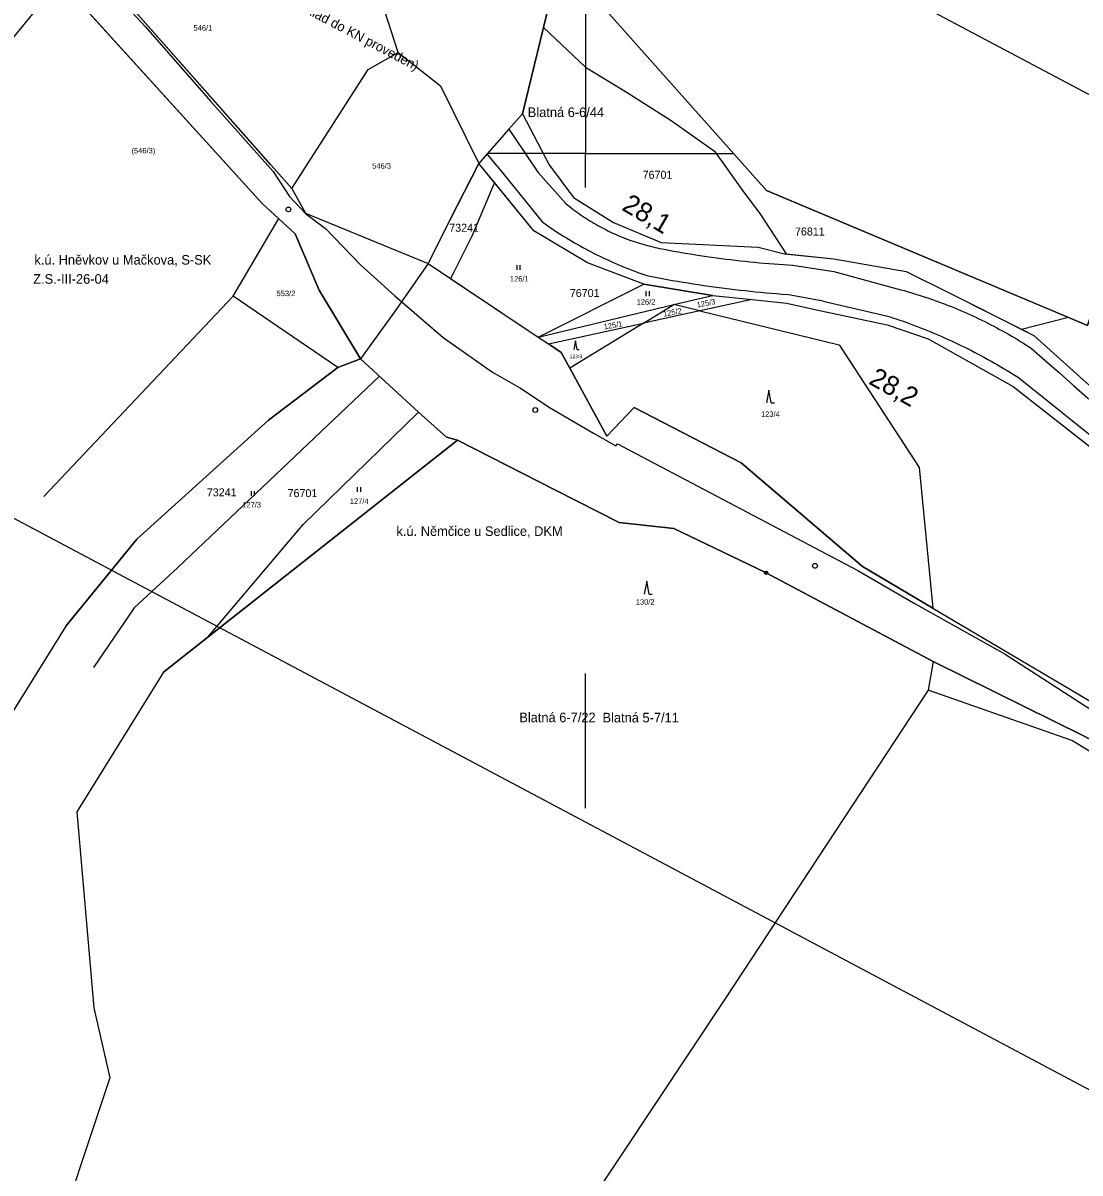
# Model space of a CAD drawing. Extents: x -794765 to -785424, y -1118958 to -1108731.
# Drawn here: x -790175.8 to -789845.5, y -1114318.6 to -1113959.3 of the extents above; entities that cross this region are included whole.
import ezdxf

# ---------------------------------------------------------------- set-up
doc = ezdxf.new("R2010")
doc.units = 0
for name, color, linetype in [('Level 66', 7, 'Continuous'), ('Level 71', 7, 'Continuous'), ('Level 73', 7, 'Continuous'), ('Level 75', 7, 'Continuous'), ('Level 76', 7, 'Continuous'), ('Level 77', 7, 'Continuous'), ('Level 78', 7, 'Continuous'), ('Level 81', 7, 'Continuous'), ('Vrstva 1', 7, 'Continuous'), ('Vrstva 53', 7, 'Continuous')]:
    doc.layers.add(name, color=color, linetype=linetype)

msp = doc.modelspace()

# ---------------------------------------------------------------- linework, layer by layer
at = {"layer": 'Level 66'}
for p, q in [((-790021.43, -1114036.41), (-790021.43, -1114034.91)), ((-790020.43, -1114036.41), (-790020.43, -1114034.91)), ((-789981.08, -1114044.59), (-789981.08, -1114043.09)), ((-789980.08, -1114044.59), (-789980.08, -1114043.09)), ((-790003.17, -1114058.6), (-790003.67, -1114061.28)), ((-790002.67, -1114061.28), (-790003.17, -1114058.6)), ((-790002.67, -1114061.28), (-790002, -1114061.28)), ((-789942.76, -1114073.96), (-789943.51, -1114077.96)), ((-789942.01, -1114077.96), (-789942.76, -1114073.96)), ((-789942.01, -1114077.96), (-789941.01, -1114077.96)), ((-790071.27, -1114105.77), (-790071.27, -1114104.27)), ((-790070.27, -1114105.77), (-790070.27, -1114104.27)), ((-790104.44, -1114107.04), (-790104.44, -1114105.54)), ((-790103.44, -1114107.04), (-790103.44, -1114105.54)), ((-789980.9, -1114133.71), (-789981.65, -1114137.71)), ((-789980.15, -1114137.71), (-789980.9, -1114133.71)), ((-789980.15, -1114137.71), (-789979.16, -1114137.71))]:
    msp.add_line(p, q, dxfattribs=at)
at = {"layer": 'Level 71'}
msp.add_line((-789259.98, -1114291.21), (-790231.6, -1113775.02), dxfattribs=at)
msp.add_lwpolyline([(-790360.41, -1114017.5), (-789388.79, -1114533.68), (-789259.98, -1114291.21)], dxfattribs=at)
at = {"layer": 'Level 75'}
for p, q in [((-790098.6, -1114003.51), (-790153.82, -1113940.85)), ((-790153.82, -1113940.85), (-790091.86, -1114010.99)), ((-790164.37, -1113945.95), (-790182.14, -1113967.7)), ((-790164.37, -1113945.95), (-790101.08, -1114015.62)), ((-790058.56, -1113968.52), (-790063.8, -1113952.28)), ((-790067.98, -1113973.75), (-790058.56, -1113968.52)), ((-790058.56, -1113968.52), (-790045.36, -1113978.94)), ((-790091.86, -1114010.99), (-790067.98, -1113973.75)), ((-790045.36, -1113978.94), (-790033.4, -1114003.11)), ((-790091.86, -1114010.99), (-790087.54, -1114018.7)), ((-790101.08, -1114015.62), (-790090.8, -1114025.12)), ((-790087.54, -1114018.7), (-790049.23, -1114034.44)), ((-790110.17, -1114044.62), (-790095.88, -1114020.36)), ((-790090.8, -1114025.12), (-790083.26, -1114042.7)), ((-790049.23, -1114034.44), (-790014.82, -1114057.41)), ((-790083.26, -1114042.7), (-790070.36, -1114064.18)), ((-790014.82, -1114057.41), (-789981.78, -1114040.88)), ((-789981.78, -1114040.88), (-789960.34, -1114044.38)), ((-790110.17, -1114044.62), (-790169.33, -1114107.22)), ((-790077.41, -1114066.92), (-790110.17, -1114044.62)), ((-790014.82, -1114057.41), (-789972.39, -1114047.26)), ((-789981.86, -1114053.04), (-789972.39, -1114047.26)), ((-789972.39, -1114047.26), (-789960.34, -1114044.38)), ((-789964.33, -1114049.22), (-789972.39, -1114047.26)), ((-789947.95, -1114045.65), (-789964.33, -1114049.22)), ((-789960.34, -1114044.38), (-789947.95, -1114045.65)), ((-789964.33, -1114049.22), (-789981.86, -1114053.04)), ((-790011.64, -1114059.53), (-789981.86, -1114053.04)), ((-789981.86, -1114053.04), (-790004.95, -1114067.14)), ((-790014.82, -1114057.41), (-790011.64, -1114059.53)), ((-790070.36, -1114064.18), (-790052.2, -1114080.82)), ((-790039.99, -1114089.61), (-790118.12, -1114151.21)), ((-789891.39, -1114158.73), (-789892.98, -1114167.7))]:
    msp.add_line(p, q, dxfattribs=at)
for points in [[(-790019.69, -1113987.62), (-790011.36, -1114003.57), (-790003.8, -1114013.73), (-789991.32, -1114021.6), (-789976.43, -1114027.83), (-789946.04, -1114029.33), (-789937.84, -1114031.36), (-789922.4, -1114032.99), (-789899.76, -1114036.89), (-789886.4, -1114043.52), (-789859.91, -1114056.9), (-789828.1, -1114085.48), (-789766.83, -1114142.08), (-789706.12, -1114193.77), (-789699.87, -1114199.39)], [(-789981.78, -1114040.88), (-789999.38, -1114034.22), (-790016.19, -1114024.23), (-790033.4, -1114003.11)], [(-789947.95, -1114045.65), (-789937.19, -1114046.76), (-789926.39, -1114049.19), (-789905.79, -1114053.58), (-789892.95, -1114057.97), (-789866.38, -1114072.87), (-789837.53, -1114095.45), (-789775.3, -1114149.42), (-789717.99, -1114202.34), (-789674.05, -1114243.92)], [(-789964.33, -1114049.22), (-789920.8, -1114059.79), (-789895.78, -1114098.15), (-789891.43, -1114142.08)], [(-790004.95, -1114067.14), (-790007.66, -1114062.18), (-790011.64, -1114059.53)], [(-789891.43, -1114142.08), (-789913.42, -1114129.06), (-789951.34, -1114096.74), (-789984.83, -1114079.42), (-789993.35, -1114088.34), (-790004.95, -1114067.14)], [(-790118.12, -1114151.21), (-790088.3, -1114115.91), (-790052.2, -1114080.82)], [(-790052.2, -1114080.82), (-790043.48, -1114088.64), (-790039.99, -1114089.61)], [(-790039.99, -1114089.61), (-790009.42, -1114105.25), (-789989.47, -1114115.38), (-789972.38, -1114117.19), (-789943.99, -1114130.82), (-789891.39, -1114158.73)], [(-789891.43, -1114142.08), (-789830.15, -1114178.38), (-789746.5, -1114225.43), (-789721.98, -1114237.82)], [(-790118.12, -1114151.21), (-790131.9, -1114162.08), (-790158.98, -1114205.72), (-790153.67, -1114267.03), (-790148.66, -1114288.87), (-790168.4, -1114348.05)], [(-789891.39, -1114158.73), (-789844.34, -1114181.96), (-789790.24, -1114210.69), (-789730.23, -1114243.59)], [(-789892.98, -1114167.7), (-789956.24, -1114263.94), (-790065.9, -1114428.82), (-790175.53, -1114594.15)], [(-789832.77, -1114192.7), (-789848.03, -1114183.45), (-789892.98, -1114167.7)]]:
    msp.add_lwpolyline(points, dxfattribs=at)
at = {"layer": 'Level 77'}
for p, q in [((-790023.95, -1113992.43), (-790022.21, -1113995.02)), ((-790022.21, -1113995.02), (-790014.92, -1114005.9)), ((-790027.64, -1114003.95), (-790030.75, -1114000.11)), ((-790027.64, -1114003.95), (-790013.47, -1114021.46)), ((-790014.92, -1114005.9), (-790006.2, -1114015.61)), ((-789935.2, -1114034.92), (-789922.4, -1114036.87)), ((-789922.4, -1114036.87), (-789901.48, -1114042.61)), ((-789925.75, -1114046.15), (-789937.07, -1114044.08)), ((-789925.75, -1114046.15), (-789905.15, -1114050.98)), ((-789835.77, -1114093.33), (-789865.26, -1114069.71))]:
    msp.add_line(p, q, dxfattribs=at)
for points in [[(-790006.2, -1114015.61), (-790005.65, -1114016.06), (-790005.09, -1114016.51), (-790004.54, -1114016.96), (-790003.97, -1114017.39), (-790003.4, -1114017.82), (-790002.83, -1114018.25), (-790002.25, -1114018.66), (-790001.67, -1114019.08), (-790001.08, -1114019.48), (-790000.49, -1114019.88), (-789999.89, -1114020.27), (-789999.29, -1114020.66), (-789998.69, -1114021.04), (-789998.08, -1114021.41), (-789997.47, -1114021.78), (-789996.85, -1114022.14), (-789996.23, -1114022.49), (-789995.6, -1114022.84), (-789994.98, -1114023.18), (-789994.35, -1114023.51), (-789993.71, -1114023.83), (-789993.07, -1114024.16), (-789992.43, -1114024.47), (-789991.79, -1114024.77), (-789991.14, -1114025.07), (-789990.49, -1114025.36), (-789989.83, -1114025.65), (-789989.18, -1114025.92), (-789988.52, -1114026.19), (-789987.85, -1114026.46), (-789987.19, -1114026.71), (-789986.52, -1114026.96), (-789985.84, -1114027.2), (-789985.17, -1114027.44), (-789984.49, -1114027.66), (-789983.82, -1114027.88), (-789983.13, -1114028.09), (-789982.45, -1114028.3), (-789981.76, -1114028.5), (-789981.08, -1114028.69), (-789980.39, -1114028.87), (-789979.7, -1114029.04), (-789979, -1114029.21), (-789978.31, -1114029.37), (-789977.61, -1114029.52), (-789976.91, -1114029.67)], [(-790013.47, -1114021.46), (-790012.66, -1114022.03), (-790011.85, -1114022.6), (-790011.03, -1114023.16), (-790010.2, -1114023.72), (-790009.38, -1114024.27), (-790008.54, -1114024.81), (-790007.71, -1114025.34), (-790006.87, -1114025.87), (-790006.02, -1114026.39), (-790005.17, -1114026.91), (-790004.32, -1114027.42), (-790003.46, -1114027.92), (-790002.6, -1114028.41), (-790001.74, -1114028.9), (-790000.87, -1114029.38), (-790000, -1114029.85), (-789999.12, -1114030.32), (-789998.24, -1114030.78), (-789997.36, -1114031.23), (-789996.47, -1114031.68), (-789995.58, -1114032.12), (-789994.69, -1114032.55), (-789993.79, -1114032.98), (-789992.89, -1114033.39), (-789991.98, -1114033.8), (-789991.08, -1114034.21), (-789990.17, -1114034.6), (-789989.25, -1114034.99), (-789988.34, -1114035.37), (-789987.42, -1114035.75), (-789986.49, -1114036.11), (-789985.57, -1114036.47), (-789984.64, -1114036.82), (-789983.71, -1114037.17), (-789982.78, -1114037.51), (-789981.84, -1114037.84), (-789980.9, -1114038.16)], [(-789976.91, -1114029.67), (-789975.44, -1114029.96), (-789973.96, -1114030.24), (-789972.48, -1114030.51), (-789971, -1114030.77), (-789969.52, -1114031.03), (-789968.04, -1114031.28), (-789966.56, -1114031.52), (-789965.07, -1114031.76), (-789963.59, -1114031.99), (-789962.1, -1114032.21), (-789960.61, -1114032.42), (-789959.13, -1114032.63), (-789957.64, -1114032.83), (-789956.15, -1114033.02), (-789954.66, -1114033.2), (-789953.16, -1114033.38), (-789951.67, -1114033.55), (-789950.18, -1114033.71), (-789948.68, -1114033.86), (-789947.19, -1114034.01), (-789945.69, -1114034.15), (-789944.19, -1114034.28), (-789942.7, -1114034.41), (-789941.2, -1114034.52), (-789939.7, -1114034.64), (-789938.2, -1114034.74), (-789936.7, -1114034.83), (-789935.2, -1114034.92)], [(-789980.9, -1114038.16), (-789979.29, -1114038.48), (-789977.68, -1114038.78), (-789976.07, -1114039.09), (-789974.46, -1114039.38), (-789972.84, -1114039.67), (-789971.23, -1114039.95), (-789969.61, -1114040.22), (-789967.99, -1114040.48), (-789966.38, -1114040.74), (-789964.76, -1114040.99), (-789963.14, -1114041.23), (-789961.51, -1114041.46), (-789959.89, -1114041.69), (-789958.27, -1114041.91), (-789956.64, -1114042.12), (-789955.01, -1114042.33), (-789953.39, -1114042.52), (-789951.76, -1114042.71), (-789950.13, -1114042.89), (-789948.5, -1114043.07), (-789946.87, -1114043.24), (-789945.24, -1114043.4), (-789943.6, -1114043.55), (-789941.97, -1114043.69), (-789940.34, -1114043.83), (-789938.71, -1114043.96), (-789937.07, -1114044.08)], [(-789901.48, -1114042.61), (-789900.47, -1114042.89), (-789899.47, -1114043.17), (-789898.47, -1114043.46), (-789897.47, -1114043.76), (-789896.47, -1114044.06), (-789895.48, -1114044.37), (-789894.49, -1114044.69), (-789893.5, -1114045.02), (-789892.51, -1114045.35), (-789891.53, -1114045.69), (-789890.54, -1114046.04), (-789889.56, -1114046.4), (-789888.59, -1114046.76), (-789887.61, -1114047.13), (-789886.64, -1114047.5), (-789885.67, -1114047.89), (-789884.71, -1114048.28), (-789883.74, -1114048.68), (-789882.78, -1114049.08), (-789881.82, -1114049.5), (-789880.87, -1114049.91), (-789879.92, -1114050.34), (-789878.97, -1114050.77), (-789878.03, -1114051.21), (-789877.08, -1114051.66), (-789876.15, -1114052.11), (-789875.21, -1114052.57), (-789874.28, -1114053.04), (-789873.35, -1114053.52), (-789872.43, -1114054), (-789871.51, -1114054.49), (-789870.59, -1114054.98), (-789869.68, -1114055.48), (-789868.77, -1114055.99), (-789867.86, -1114056.51), (-789866.96, -1114057.03), (-789866.06, -1114057.55), (-789865.16, -1114058.09), (-789864.27, -1114058.63), (-789863.39, -1114059.18), (-789862.5, -1114059.73), (-789861.62, -1114060.29), (-789860.75, -1114060.86)], [(-789905.15, -1114050.98), (-789904.05, -1114051.34), (-789902.94, -1114051.71), (-789901.84, -1114052.09), (-789900.74, -1114052.47), (-789899.65, -1114052.86), (-789898.56, -1114053.26), (-789897.47, -1114053.66), (-789896.38, -1114054.07), (-789895.29, -1114054.49), (-789894.21, -1114054.92), (-789893.13, -1114055.35), (-789892.06, -1114055.8), (-789890.98, -1114056.24), (-789889.92, -1114056.7), (-789888.85, -1114057.16), (-789887.78, -1114057.63), (-789886.72, -1114058.11), (-789885.67, -1114058.59), (-789884.61, -1114059.08), (-789883.56, -1114059.58), (-789882.51, -1114060.08), (-789881.47, -1114060.6), (-789880.43, -1114061.11), (-789879.39, -1114061.64), (-789878.36, -1114062.17), (-789877.33, -1114062.71), (-789876.3, -1114063.26), (-789875.28, -1114063.81), (-789874.26, -1114064.37), (-789873.24, -1114064.94), (-789872.23, -1114065.51), (-789871.22, -1114066.09), (-789870.22, -1114066.68), (-789869.22, -1114067.27), (-789868.22, -1114067.87), (-789867.23, -1114068.48), (-789866.24, -1114069.09), (-789865.26, -1114069.71)], [(-789860.75, -1114060.86), (-789856.33, -1114064.74), (-789851.91, -1114068.61), (-789847.5, -1114072.5), (-789843.09, -1114076.39), (-789838.69, -1114080.29), (-789834.29, -1114084.19), (-789829.9, -1114088.1), (-789825.52, -1114092.02), (-789821.13, -1114095.94), (-789816.76, -1114099.86), (-789812.39, -1114103.79), (-789808.02, -1114107.73), (-789803.66, -1114111.67), (-789799.3, -1114115.62), (-789794.95, -1114119.57), (-789790.6, -1114123.53), (-789786.26, -1114127.5), (-789781.93, -1114131.47), (-789777.6, -1114135.44), (-789773.27, -1114139.42), (-789768.95, -1114143.41)]]:
    msp.add_lwpolyline(points, dxfattribs=at)
at = {"layer": 'Level 78'}
for p, q in [((-790033.4, -1114003.11), (-790042.39, -1114020.89)), ((-790042.39, -1114020.89), (-790049.23, -1114034.44)), ((-790049.23, -1114034.44), (-790059.73, -1114049.47)), ((-790059.73, -1114049.47), (-790070.36, -1114064.18))]:
    msp.add_line(p, q, dxfattribs=at)
for points in [[(-789943.45, -1114011.64), (-790007.99, -1113939.1), (-790019.69, -1113987.62)], [(-790019.69, -1113987.62), (-790023.95, -1113992.43), (-790030.75, -1114000.11), (-790033.4, -1114003.11)], [(-789834.61, -1114027.84), (-789843.16, -1114053.8), (-789943.45, -1114011.64)], [(-790070.36, -1114064.18), (-790077.41, -1114066.92), (-790099.13, -1114083.32), (-790140.29, -1114120.5), (-790162.46, -1114147.73), (-790179, -1114174.35), (-790192.46, -1114201.21), (-790195.44, -1114214.86), (-790192.12, -1114271.28), (-790194.98, -1114295.25), (-790216.55, -1114326.64), (-790237.66, -1114340.78), (-790265.88, -1114352.25), (-790307.31, -1114357.21), (-790358.52, -1114379.07), (-790378.06, -1114396.2)]]:
    msp.add_lwpolyline(points, dxfattribs=at)
at = {"layer": 'Level 81'}
for p, q in [((-790019.69, -1113987.62), (-790013.2, -1113960.7)), ((-790028.5, -1114009.12), (-790033.4, -1114003.11)), ((-789945.59, -1114018.79), (-789937.34, -1114031.41)), ((-790049.23, -1114034.44), (-790042.18, -1114039.14)), ((-790041.35, -1114037.5), (-790042.18, -1114039.14)), ((-789863.72, -1114054.97), (-789849.48, -1114051.25)), ((-789849.48, -1114051.25), (-789849.33, -1114051.2))]:
    msp.add_line(p, q, dxfattribs=at)
for points in [[(-790013.2, -1113960.7), (-790007.99, -1113939.1), (-789943.45, -1114011.64), (-789849.33, -1114051.2)], [(-790013.2, -1113960.7), (-790000.03, -1113973.03), (-790000, -1113973.05), (-789987.02, -1113981.02), (-789973.21, -1113989.77), (-789959.71, -1113999.32), (-789959.23, -1114000), (-789950.67, -1114012), (-789945.59, -1114018.79)], [(-790019.69, -1113987.62), (-790011.36, -1114003.57), (-790003.8, -1114013.73), (-789991.32, -1114021.6), (-789976.43, -1114027.83), (-789946.04, -1114029.33), (-789937.84, -1114031.36), (-789937.34, -1114031.41)], [(-790049.23, -1114034.44), (-790042.39, -1114020.89), (-790033.4, -1114003.11)], [(-790028.5, -1114009.12), (-790035.41, -1114025.68), (-790041.35, -1114037.5)], [(-789972.39, -1114047.26), (-789960.34, -1114044.38), (-789981.78, -1114040.88), (-789999.38, -1114034.22), (-790016.19, -1114024.23), (-790028.5, -1114009.12)], [(-789937.34, -1114031.41), (-789922.4, -1114032.99), (-789899.76, -1114036.89), (-789886.4, -1114043.52), (-789863.72, -1114054.97)], [(-790042.18, -1114039.14), (-790014.82, -1114057.41), (-789972.39, -1114047.26)], [(-789849.33, -1114051.2), (-789843.16, -1114053.8), (-789841.6, -1114049.06)], [(-789863.72, -1114054.97), (-789859.91, -1114056.9), (-789828.1, -1114085.48), (-789766.83, -1114142.08), (-789706.12, -1114193.77), (-789699.87, -1114199.39), (-789653.29, -1114241.26), (-789626.24, -1114265.44), (-789585.72, -1114278.05), (-789547.28, -1114285.86), (-789509.8, -1114297.51), (-789475.21, -1114308.57), (-789456.17, -1114314.65), (-789451.67, -1114316.09), (-789445.82, -1114299.21), (-789436.06, -1114282.16), (-789435.21, -1114282.44), (-789432.19, -1114273.58), (-789444.18, -1114268.92), (-789455.16, -1114266.24)], [(-790162.46, -1114147.73), (-790140.29, -1114120.5), (-790099.13, -1114083.32), (-790077.41, -1114066.92), (-790070.36, -1114064.18)], [(-790131.9, -1114162.08), (-790118.12, -1114151.21), (-790039.99, -1114089.61), (-790043.48, -1114088.64), (-790052.2, -1114080.82), (-790070.36, -1114064.18)], [(-790064.44, -1114069.6), (-790127.48, -1114129.4), (-790141.06, -1114142.04), (-790153.79, -1114160.6)]]:
    msp.add_lwpolyline(points, dxfattribs=at)
at = {"layer": 'Vrstva 1'}
for p, q in [((-790154.38, -1113942.38), (-790137.55, -1113960.43)), ((-790000, -1113948.08), (-790000, -1114000)), ((-790137.55, -1113960.43), (-790117.25, -1113983.63)), ((-790000, -1114000), (-790030.65, -1114000)), ((-790000, -1114000), (-789953.81, -1114000)), ((-790000, -1114010.65), (-790000, -1114000)), ((-790000, -1114204.62), (-790000, -1114162.49))]:
    msp.add_line(p, q, dxfattribs=at)
for points in [[(-790117.25, -1113983.63), (-790097.65, -1114005.61)], [(-790097.65, -1114005.61), (-790092.51, -1114013.51), (-790087.58, -1114018.78), (-790081.27, -1114023.48), (-790070.39, -1114034.8), (-790059.64, -1114044.51), (-790044.53, -1114057.48), (-790029.1, -1114068.39), (-790020.34, -1114073.4), (-790011.12, -1114079.5), (-789997.53, -1114087.43), (-789990.59, -1114091.36), (-789990, -1114090.71), (-789957.24, -1114108), (-789914.92, -1114130.33), (-789897.47, -1114140.42), (-789868.89, -1114156.49), (-789842.11, -1114173.75), (-789808.41, -1114192.36), (-789781.82, -1114206.71), (-789745.94, -1114226.72), (-789729.37, -1114235.18)]]:
    msp.add_lwpolyline(points, dxfattribs=at)
for centre in [(-790092.88, -1114017.5), (-790015.75, -1114080.18), (-789928.3, -1114128.88)]:
    msp.add_circle(centre, 0.75, dxfattribs=at)
at = {"layer": 'Vrstva 53'}
msp.add_line((-789943.63, -1114131.02), (-789943.55, -1114131.07), dxfattribs=at)
for points in [[(-790070.36, -1114064.18), (-790083.26, -1114042.7), (-790090.8, -1114025.12), (-790101.08, -1114015.62), (-790164.37, -1113945.95), (-790187.33, -1113924.36), (-790227.79, -1113892.5), (-790270.49, -1113867.67), (-790266.88, -1113856.5)], [(-790266.88, -1113856.5), (-790264.64, -1113859.59), (-790239.37, -1113873.47), (-790222.82, -1113883.58), (-790209.83, -1113891.74), (-790184.25, -1113912.16), (-790158.65, -1113935.51), (-790153.82, -1113940.85), (-790091.86, -1114010.99), (-790087.54, -1114018.7), (-790049.23, -1114034.44)], [(-790049.23, -1114034.44), (-790014.82, -1114057.41), (-790011.64, -1114059.53), (-790007.66, -1114062.18), (-790004.95, -1114067.14), (-789993.35, -1114088.34), (-789984.83, -1114079.42), (-789951.34, -1114096.74), (-789913.42, -1114129.06), (-789891.43, -1114142.08), (-789830.15, -1114178.38), (-789746.5, -1114225.43), (-789721.98, -1114237.82), (-789717.72, -1114240.35), (-789691.28, -1114256.01), (-789665.23, -1114268.84), (-789640.19, -1114272.7), (-789627.07, -1114282.33), (-789607.19, -1114286.63), (-789603.91, -1114286.39)], [(-789600.46, -1114294.39), (-789619.3, -1114290.36), (-789624.34, -1114291.37), (-789641.23, -1114287.32), (-789672.68, -1114277.31), (-789675.34, -1114276.11), (-789724.61, -1114250.58), (-789730.23, -1114243.59), (-789790.24, -1114210.69), (-789844.34, -1114181.96), (-789891.39, -1114158.73), (-789943.99, -1114130.82), (-789972.38, -1114117.19), (-789989.47, -1114115.38), (-790009.42, -1114105.25), (-790039.99, -1114089.61), (-790043.48, -1114088.64), (-790052.2, -1114080.82), (-790070.36, -1114064.18)]]:
    msp.add_lwpolyline(points, dxfattribs=at)
msp.add_circle((-789943.59, -1114131.04), 0.499, dxfattribs=at)

# ---------------------------------------------------------------- texts
at = {"layer": 'Level 73'}
for s, rotation, p in [('28,1', 329.6447, (-789989.01, -1114017.5)), ('28,2', 330.9437, (-789911.85, -1114071.84))]:
    msp.add_text(s, height=6, rotation=rotation, dxfattribs=at).set_placement(p)
at = {"layer": 'Level 75'}
msp.add_text('(546/3)', height=1.7, dxfattribs=at).set_placement((-790141.93, -1114000))
at = {"layer": 'Level 76'}
for s, height, p in [('546/1', 1.7, (-790122.55, -1113961.62)), ('546/3', 1.7, (-790066.71, -1114004.76)), ('126/1', 1.7, (-790023.66, -1114040.02)), ('553/2', 1.7, (-790096.59, -1114044.6)), ('126/2', 1.7, (-789984.05, -1114047.26)), ('123/3', 1.14, (-790005.01, -1114064)), ('123/4', 1.7, (-789945.19, -1114082.32)), ('127/3', 1.7, (-790107.32, -1114110.64)), ('127/4', 1.7, (-790073.69, -1114109.54)), ('130/2', 1.7, (-789984.31, -1114141))]:
    msp.add_text(s, height=height, dxfattribs=at).set_placement(p)
for s, rotation, p in [('125/3', 11, (-789965.09, -1114048.19)), ('125/2', 11, (-789975.59, -1114051.05)), ('125/1', 10, (-789994.17, -1114055.04))]:
    msp.add_text(s, height=1.7, rotation=rotation, dxfattribs=at).set_placement(p)
at = {"layer": 'Level 78'}
for s, p in [('k.ú. Hněvkov u Mačkova, S-SK', (-790172.28, -1114034.75)), ('k.ú. Němčice u Sedlice, DKM', (-790059.11, -1114119.53))]:
    msp.add_text(s, height=3, dxfattribs=at).set_placement(p)
at = {"layer": 'Level 81'}
for s, p in [('76701', (-789982.18, -1114007.94)), ('73241', (-790042.63, -1114024.49)), ('76811', (-789934.56, -1114025.66)), ('76701', (-790004.93, -1114044.88)), ('73241', (-790118.39, -1114107.16)), ('76701', (-790093.14, -1114107.41))]:
    msp.add_text(s, height=2.5, dxfattribs=at).set_placement(p)
at = {"layer": 'Vrstva 1'}
msp.add_text('věcné břemeno VB-06 (vklad do KN proveden)', height=3, rotation=332.3541, dxfattribs=at).set_placement((-790126.8, -1113935.62))
for s, p in [('Blatná 6-6/44', (-790018.08, -1113988.64)), ('Z.S.-III-26-04', (-790172.65, -1114040.73)), ('Blatná 6-7/22', (-790020.73, -1114177.74)), ('Blatná 5-7/11', (-789994.72, -1114177.8))]:
    msp.add_text(s, height=3, dxfattribs=at).set_placement(p)

doc.saveas('drawing.dxf')
